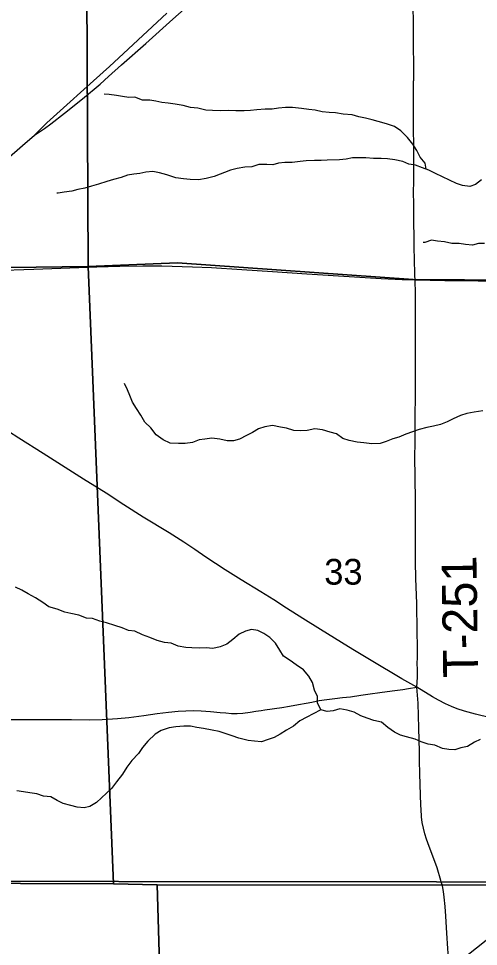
# Model space of a CAD drawing. Extents: x 1874609 to 2204689, y 815661 to 1281160.
# Drawn here: x 2054716 to 2058665, y 1056338 to 1064307 of the extents above; entities that cross this region are included whole.
import ezdxf

# ---------------------------------------------------------------- set-up
doc = ezdxf.new("R2010")
doc.units = 0
for name, color, linetype in [('GM_X_County_Road', 7, 'Continuous'), ('GM_X_Interstate_Route', 7, 'Continuous'), ('GM_X_Minor_River', 7, 'Continuous'), ('GM_X_Section', 7, 'Continuous'), ('GM_X_Section_Text', 7, 'Continuous'), ('GM_X_State_Route', 7, 'Continuous'), ('GM_X_Township', 7, 'Continuous'), ('GM_X_Township_Road', 7, 'Continuous'), ('GM_X_Township_Road_Text', 7, 'Continuous'), ('GM_X_US_Route', 7, 'Continuous')]:
    doc.layers.add(name, color=color, linetype=linetype)

msp = doc.modelspace()

# ---------------------------------------------------------------- linework, layer by layer
at = {"layer": 'GM_X_County_Road'}
for points in [[(2058346.2, 1056891.4), (2058343.1, 1056903.7), (2058309.6, 1057011.5), (2058282.9, 1057088.8), (2058241.5, 1057195.9), (2058219, 1057257.7), (2058204.4, 1057304.9), (2058192.3, 1057352.9), (2058182.9, 1057401.5), (2058176.4, 1057450.5), (2058172.1, 1057515.8), (2058170.8, 1057548.1), (2058168.1, 1057643.8), (2058165.8, 1057726.2), (2058163, 1057825.3), (2058160.1, 1057929.2), (2058157.7, 1058015), (2058155, 1058110.6), (2058152.1, 1058214.7), (2058149.2, 1058316.9), (2058146.2, 1058426), (2058136.1, 1058563.2)], [(2058526.5, 1054148.8), (2058526, 1054159.3), (2058513.9, 1054388.6), (2058505.7, 1054536), (2058495.1, 1054749), (2058476.4, 1055060.1), (2058458.6, 1055354.8), (2058450.8, 1055485.8), (2058442.2, 1055633.1), (2058429.4, 1055829.3), (2058423, 1055943.9), (2058419.5, 1056012.5), (2058413.1, 1056138.4), (2058412.2, 1056156.8), (2058407, 1056238.6), (2058401.4, 1056320.2), (2058393.2, 1056450.9), (2058385, 1056598.2), (2058379.8, 1056679.7), (2058372, 1056761), (2058364.8, 1056809.4), (2058354.9, 1056856.9), (2058346.2, 1056891.4)]]:
    msp.add_lwpolyline(points, dxfattribs=at)
at = {"layer": 'GM_X_Interstate_Route'}
msp.add_lwpolyline([(2058563.9, 1056260.9), (2058731.4, 1056392.6)], dxfattribs=at)
at = {"layer": 'GM_X_Minor_River'}
for points in [[(2058215.3, 1063012.1), (2058206.3, 1063063.9), (2058164.7, 1063116.4), (2058137.2, 1063174.8), (2058101.7, 1063229.2), (2058056.2, 1063285.8), (2057998.7, 1063342.4), (2057945, 1063381), (2057875.2, 1063401.7), (2057803.4, 1063422.4), (2057751.6, 1063437), (2057693.7, 1063451.6), (2057637.8, 1063464.1), (2057580, 1063478.7), (2057504, 1063485.4), (2057438.2, 1063496.1), (2057382.2, 1063498.7), (2057322.3, 1063505.2), (2057262.4, 1063519.9), (2057208.5, 1063526.4), (2057144.6, 1063533), (2057068.7, 1063541.8), (2057008.7, 1063542.4), (2056948.7, 1063536.9), (2056892.6, 1063529.5), (2056832.6, 1063528.1), (2056762.6, 1063522.7), (2056706.6, 1063517.2), (2056652.6, 1063515.8), (2056582.6, 1063514.5), (2056522.6, 1063517.1), (2056446.6, 1063515.8), (2056380.7, 1063516.4), (2056324.7, 1063519), (2056254.9, 1063537.7), (2056192.9, 1063544.3), (2056129.1, 1063558.9), (2056061.2, 1063571.6), (2056001.3, 1063580.2), (2055947.4, 1063584.8), (2055895.5, 1063597.3), (2055843.6, 1063605.8), (2055779.6, 1063606.4), (2055713.8, 1063631.1), (2055661.8, 1063627.6), (2055607.9, 1063636.1), (2055556, 1063646.7), (2055494.1, 1063653.3), (2055452.1, 1063657.7)], [(2058690.9, 1062923), (2058640.6, 1062881.4), (2058590.5, 1062865.9), (2058528.5, 1062872.5), (2058476.7, 1062889), (2058415, 1062919.6), (2058355.2, 1062948.3), (2058295.5, 1062974.9), (2058237.7, 1063003.5), (2058183.9, 1063024.1), (2058124.1, 1063046.7), (2058066.2, 1063057.3), (2058014.4, 1063077.8), (2057946.6, 1063092.5), (2057882.7, 1063101.1), (2057828.7, 1063103.7), (2057764.7, 1063104.3), (2057698.8, 1063110.9), (2057636.8, 1063111.5), (2057584.9, 1063112), (2057528.8, 1063098.6), (2057472.7, 1063093.1), (2057366.7, 1063090.1), (2057314.7, 1063088.6), (2057256.7, 1063087.2), (2057186.7, 1063083.9), (2057134.7, 1063080.4), (2057064.7, 1063071), (2057002.7, 1063069.6), (2056948.7, 1063066.1), (2056898.5, 1063050.6), (2056846.6, 1063053.1), (2056780.6, 1063053.8), (2056718.4, 1063034.3), (2056658.4, 1063030.9), (2056594.4, 1063019.5), (2056536.2, 1063004.1), (2056395.8, 1062949.3), (2056327.7, 1062932), (2056261.6, 1062922.6), (2056189.7, 1062925.3), (2056131.7, 1062929.9), (2056065.8, 1062938.5), (2055988.1, 1062965.3), (2055926.2, 1062981.9), (2055868.3, 1062992.5), (2055808.3, 1062987.1), (2055756.2, 1062975.6), (2055706.2, 1062970.1), (2055652.1, 1062960.6), (2055596, 1062941.1), (2055529.9, 1062923.7), (2055473.7, 1062908.2), (2055403.6, 1062884.9), (2055343.4, 1062867.4), (2055285.3, 1062850), (2055225.2, 1062838.5), (2055173.1, 1062825), (2055107.1, 1062815.6)], [(2055107.1, 1062815.6), (2055057, 1062808.1), (2055045, 1062808.2)], [(2058718.2, 1062373.8), (2058664.3, 1062374.3), (2058614.2, 1062360.8), (2058554.2, 1062367.4), (2058500.3, 1062375.9), (2058436.3, 1062374.5), (2058372.5, 1062389.2), (2058314.5, 1062393.7), (2058260.6, 1062402.3), (2058204.5, 1062384.8), (2058190.5, 1062384.9)], [(2056672.8, 1060724.8), (2056612.6, 1060693.4), (2056560.5, 1060679.9), (2056506.5, 1060680.4), (2056444.7, 1060695), (2056376.8, 1060703.7), (2056316.7, 1060694.3), (2056266.7, 1060688.7), (2056210.5, 1060667.2), (2056146.4, 1060655.8), (2056090.5, 1060658.4), (2056018.5, 1060661.1), (2055956.8, 1060689.8), (2055897.1, 1060730.4), (2055851.7, 1060792.9), (2055800.1, 1060839.5), (2055766.6, 1060900), (2055729.1, 1060958.4), (2055693.6, 1061010.9), (2055672.1, 1061069.2), (2055650.5, 1061119.5), (2055624.9, 1061171.8), (2055627, 1061173.8)], [(2058702, 1060937.5), (2058628, 1060926.2), (2058565.9, 1060914.8), (2058509.8, 1060897.3), (2058447.5, 1060869.8), (2058397.3, 1060842.3), (2058339.2, 1060820.8), (2058279.1, 1060807.4), (2058223, 1060795.9), (2058156.8, 1060776.5), (2058098.7, 1060757), (2058042.5, 1060737.5), (2057982.3, 1060712.1), (2057930.3, 1060698.6), (2057872.1, 1060673.1), (2057821.9, 1060657.6), (2057749.9, 1060654.2), (2057682, 1060662.9), (2057624.1, 1060667.5), (2057556.2, 1060684.2), (2057500.4, 1060700.8), (2057444.7, 1060739.4), (2057392.9, 1060755.9), (2057327.1, 1060774.6), (2057261.2, 1060783.2), (2057193.1, 1060767.8), (2057137.1, 1060766.4), (2057079.1, 1060769), (2057017.3, 1060787.6), (2056965.4, 1060796.1), (2056895.5, 1060810.8), (2056831.4, 1060801.4), (2056775.3, 1060781.9), (2056725, 1060750.4), (2056672.8, 1060724.8)], [(2058680.1, 1058114.8), (2058629.9, 1058091.2), (2058569.6, 1058055.8), (2058513.5, 1058042.3), (2058463.4, 1058026.8), (2058409.5, 1058029.3), (2058357.5, 1058037.8), (2058291.8, 1058066.5), (2058231.9, 1058075.1), (2058174.1, 1058095.7), (2058120.3, 1058118.2), (2058046.5, 1058137), (2057994.6, 1058153.5), (2057942.9, 1058178.1), (2057887.2, 1058218.7), (2057831.6, 1058263.3), (2057767.8, 1058277.9), (2057710, 1058298.6), (2057656.1, 1058317.1), (2057598.4, 1058349.7), (2057536.6, 1058366.4), (2057474.7, 1058377), (2057418.6, 1058361.5), (2057366.5, 1058356), (2057312.7, 1058368.5), (2057283.2, 1058430.9), (2057281.7, 1058485.1), (2057258.1, 1058537.4), (2057240.7, 1058605.6), (2057207.2, 1058660.1), (2057161.6, 1058712.6), (2057100, 1058755.3), (2057048.3, 1058793.8), (2056990.7, 1058830.5), (2056959.1, 1058882.9), (2056921.6, 1058941.3), (2056874.1, 1058991.9), (2056822.4, 1059026.5), (2056770.6, 1059051), (2056716.7, 1059059.5), (2056664.6, 1059046), (2056610.4, 1059020.5), (2056556, 1058973), (2056503.7, 1058933.4), (2056447.5, 1058909.9), (2056385.4, 1058896.5), (2056327.5, 1058901.1), (2056271.5, 1058899.6), (2056203.5, 1058902.3), (2056151.5, 1058904.8), (2056087.7, 1058917.4), (2056025.9, 1058942.1), (2055970, 1058948.6), (2055906.1, 1058965.3), (2055844.4, 1058989.9), (2055780.6, 1059012.6), (2055714.9, 1059045.3), (2055658.9, 1059049.8), (2055607.1, 1059074.4), (2055541.3, 1059093.1), (2055471.5, 1059115.8), (2055413.7, 1059132.4), (2055351.9, 1059153), (2055299.9, 1059157.5), (2055234.2, 1059184.2), (2055166.3, 1059196.9), (2055114.4, 1059209.4), (2055048.6, 1059234.1), (2054976.8, 1059254.8), (2054923.2, 1059291.4), (2054861.5, 1059332.1), (2054799.8, 1059364.7), (2054744.1, 1059397.3), (2054688.4, 1059423.9)], [(2057312.7, 1058368.5), (2057244.4, 1058335.1), (2057190.2, 1058307.6), (2057131.9, 1058274.1), (2057075.5, 1058228.6), (2057017.3, 1058195.1), (2056961, 1058161.6), (2056910.8, 1058132.1), (2056858.6, 1058114.5), (2056802.5, 1058095), (2056742.6, 1058101.6), (2056686.6, 1058106.2), (2056608.8, 1058127), (2056551, 1058145.6), (2056491.2, 1058166.2), (2056439.3, 1058184.7), (2056377.5, 1058195.3), (2056303.6, 1058210.1), (2056245.7, 1058218.7), (2056193.8, 1058229.2), (2056133.8, 1058229.8), (2056067.8, 1058224.4), (2056009.7, 1058215), (2055941.6, 1058193.6), (2055889.3, 1058160), (2055826.8, 1058100.6), (2055780.4, 1058046.9), (2055745.9, 1057995.1), (2055687.5, 1057935.6), (2055645, 1057877.9), (2055608.5, 1057818.2), (2055555.9, 1057752.6), (2055513.4, 1057692.9), (2055384.5, 1057573.9), (2055328.2, 1057538.4), (2055278.1, 1057526.9), (2055220.2, 1057533.5), (2055166.3, 1057548), (2055098.5, 1057566.7), (2055046.7, 1057591.3), (2054993, 1057621.8), (2054929.1, 1057628.5), (2054873.2, 1057647.1), (2054813.3, 1057655.6), (2054757.4, 1057666.2), (2054701.5, 1057672.8)]]:
    msp.add_lwpolyline(points, dxfattribs=at)
at = {"layer": 'GM_X_Section'}
for points in [[(2055287, 1067524.1), (2055313.6, 1062177.1), (2052406, 1062140.9), (2050158.4, 1062213.2), (2050065.8, 1067532)], [(2060730.3, 1067523), (2060745.3, 1062047.8), (2058105.7, 1062064.7), (2056081.9, 1062209.8), (2055313.6, 1062177.1), (2055287, 1067524.1)], [(2055313.6, 1062177.1), (2055530.1, 1056876.8), (2050743.2, 1056892.2), (2050194.9, 1056904.2), (2050158.4, 1062213.2), (2052406, 1062140.9)], [(2060745.3, 1062047.8), (2060833.3, 1056863.1), (2055906.4, 1056868), (2055530.1, 1056876.8), (2055313.6, 1062177.1), (2056081.9, 1062209.8), (2058105.7, 1062064.7)], [(2055530.1, 1056876.8), (2055906.4, 1056868), (2056063, 1051515.5), (2051042.8, 1051308), (2050743.2, 1056892.2)], [(2061121.5, 1056856.1), (2061308.2, 1051483.6), (2056063, 1051515.5), (2055906.4, 1056868), (2060833.3, 1056863.1)]]:
    msp.add_lwpolyline(points, close=True, dxfattribs=at)
at = {"layer": 'GM_X_State_Route'}
for points in [[(2054503.2, 1062143.5), (2054847.6, 1062155.5), (2055388.8, 1062173.5), (2055585.6, 1062178.9), (2055782.3, 1062182.4), (2055946.2, 1062182.4), (2056208.5, 1062175.1), (2056372.3, 1062168.7), (2056634.1, 1062152.7), (2056895.9, 1062133.9), (2057190.7, 1062114.2), (2057600, 1062087.4), (2057829.4, 1062073.9), (2058009.7, 1062065), (2058121.9, 1062061.6), (2058376.1, 1062057.3), (2058663.6, 1062054.8), (2058983.3, 1062054.7)], [(2058767.3, 1058302.3), (2058640.1, 1058333), (2058545.3, 1058357.8), (2058481.8, 1058379.4), (2058434.7, 1058398.3), (2058382.9, 1058421.9), (2058321.7, 1058453.9), (2058269.9, 1058482.2), (2058136.1, 1058563.2), (2058007, 1058635.7), (2057742.5, 1058794.7), (2057587.6, 1058887), (2057489.9, 1058947), (2057308.6, 1059059.4), (2057155.9, 1059155.3), (2057017.7, 1059243.8), (2056907.1, 1059314.4), (2056795.9, 1059383.9), (2056627.3, 1059485.5), (2056489, 1059573.5), (2056323.7, 1059680.1), (2056230, 1059745.9), (2056134.7, 1059810.4), (2056009.3, 1059888.6), (2055785.3, 1060025.3), (2055619.6, 1060131.6), (2055467.9, 1060229.3), (2055273.4, 1060351.8), (2054926.2, 1060570.1), (2054718.6, 1060702.2), (2054538.4, 1060816.3)]]:
    msp.add_lwpolyline(points, dxfattribs=at)
at = {"layer": 'GM_X_Township'}
for points in [[(2071122.1, 1077956.3), (2071255.1, 1071443.9), (2071304.4, 1070159.8), (2071270.7, 1069576.7), (2071181.7, 1067473.1), (2071243.1, 1064399.7), (2071288.2, 1062148.4), (2071392.9, 1056914.6), (2063510.6, 1056885.7), (2061446.3, 1056888.3), (2059528.3, 1056890.6), (2058304.2, 1056892.2), (2052843.3, 1056898.9), (2047828.1, 1056905.1), (2047574.2, 1056905.4), (2045481.2, 1056908), (2044859.9, 1056908.1), (2044746.9, 1064387.8), (2044699.1, 1067550.3), (2044618.5, 1072885.8), (2044539, 1078146.3)], [(2045478.3, 1056323.1), (2045481.2, 1056908), (2047574.2, 1056905.4), (2047828.1, 1056905.1), (2052843.3, 1056898.9), (2058304.2, 1056892.2), (2059528.3, 1056890.6), (2061446.3, 1056888.3), (2063510.6, 1056885.7), (2071392.9, 1056914.6), (2071559.1, 1056912.2), (2071772.3, 1055613.7)]]:
    msp.add_lwpolyline(points, dxfattribs=at)
at = {"layer": 'GM_X_Township_Road'}
for points in [[(2058121.9, 1062061.6), (2058120.1, 1062101.3), (2058115.1, 1062248.2), (2058114.1, 1062330), (2058112.8, 1062411.9), (2058110.1, 1062575.6), (2058110.2, 1062624.7), (2058109.5, 1062723), (2058108.1, 1062804.8), (2058109.4, 1062919.5), (2058110.3, 1063083.1), (2058111.2, 1063165), (2058110.1, 1063230.8), (2058107.8, 1063345.4), (2058106.9, 1063427.1), (2058106.6, 1063525), (2058106.7, 1063606.7), (2058106.5, 1063704.9), (2058107.5, 1063736.2), (2058107.5, 1063753.9), (2058108.4, 1063767.8), (2058111, 1063778.4), (2058109.9, 1063792.5), (2058109.8, 1063841.9), (2058109, 1063923.8), (2058107.2, 1064054.7), (2058107.7, 1064136.6), (2058108.2, 1064202.2), (2058106.3, 1064284.1), (2058105.8, 1064398.7)], [(2058136.1, 1058563.2), (2058139.9, 1058606.5), (2058142.1, 1058649), (2058140.6, 1058708.1), (2058139.9, 1058776.7), (2058140.6, 1058809.7), (2058142.2, 1058867.3), (2058140.7, 1058938.5), (2058139.2, 1059012.8), (2058139.2, 1059091.6), (2058137.6, 1059134), (2058136.1, 1059191.6), (2058136.1, 1059229.5), (2058136.4, 1059284.2), (2058128.2, 1059497), (2058125.5, 1059644.3), (2058125.3, 1059742.6), (2058125.8, 1059873.7), (2058125.1, 1060054.1), (2058124.1, 1060185.2), (2058122, 1060349.2), (2058121.1, 1060414.7), (2058119.8, 1060496.5), (2058119.3, 1060561.5), (2058120.3, 1060643), (2058120.5, 1060708.4), (2058121.1, 1060774), (2058121.9, 1060839.4), (2058123, 1060937.5), (2058124.4, 1061019.3), (2058124.8, 1061084.9), (2058125.8, 1061166.9), (2058124.3, 1061281.7), (2058124.5, 1061412.7), (2058125.3, 1061625.9), (2058124.7, 1061757), (2058123.7, 1061953.7), (2058122.4, 1062052.2), (2058121.9, 1062061.6)], [(2054478.7, 1058288), (2054726.1, 1058287.9), (2055170.2, 1058285.7), (2055324.9, 1058283.4), (2055434.5, 1058285.7), (2055565.3, 1058294.2), (2055663.1, 1058303.9), (2055793, 1058320.8), (2055906.5, 1058337.7), (2056004.3, 1058350.9), (2056086.1, 1058358.6), (2056151.8, 1058362.6), (2056217.5, 1058363.9), (2056283.2, 1058362.1), (2056365.1, 1058356.1), (2056446.8, 1058347.9), (2056495.6, 1058342.7), (2056544.3, 1058339.2), (2056592.9, 1058339.2), (2056641.4, 1058342), (2056705.3, 1058349.6), (2056752.1, 1058357.2), (2056799.1, 1058365.1), (2056830.8, 1058370.6), (2056976.7, 1058391.2), (2057041.6, 1058402.5), (2057118.9, 1058415.8), (2057186.1, 1058426.4), (2057234.2, 1058436.9), (2057298.3, 1058449.5), (2057363.4, 1058457.7), (2057430.4, 1058466.6), (2057498.9, 1058475.4), (2057565.2, 1058482), (2057655.8, 1058495.3), (2057736.6, 1058505.9), (2057818, 1058517.4), (2057925.3, 1058532.8), (2058015.9, 1058543.8), (2058064.5, 1058552.6), (2058136.1, 1058563.2)]]:
    msp.add_lwpolyline(points, dxfattribs=at)
at = {"layer": 'GM_X_US_Route'}
for points in [[(2054570.3, 1063060.1), (2054614.8, 1063099), (2054751.2, 1063217.3), (2054854.3, 1063305.2), (2054939.2, 1063361.8), (2054993.9, 1063402.4), (2055111.9, 1063494.8), (2055265.2, 1063617), (2055415.8, 1063743.8), (2055489.2, 1063809.2), (2055598.7, 1063908.4), (2055807.5, 1064093.4), (2056040.6, 1064300.6), (2056187.4, 1064431.8)], [(2054854.3, 1063305.2), (2054959, 1063410.9), (2055131.2, 1063566), (2055277.3, 1063698), (2055496.9, 1063895.6), (2055617.7, 1064006.8), (2055990.5, 1064352.8)]]:
    msp.add_lwpolyline(points, dxfattribs=at)

# ---------------------------------------------------------------- texts
at = {"layer": 'GM_X_Section_Text'}
msp.add_text('33', height=221, rotation=0.00001, dxfattribs=at).set_placement((2057341.1, 1059445))
at = {"layer": 'GM_X_Township_Road_Text'}
msp.add_text('T-251', height=300, rotation=90.83092, dxfattribs=at).set_placement((2058662.6, 1058647.2))

doc.saveas('drawing.dxf')
